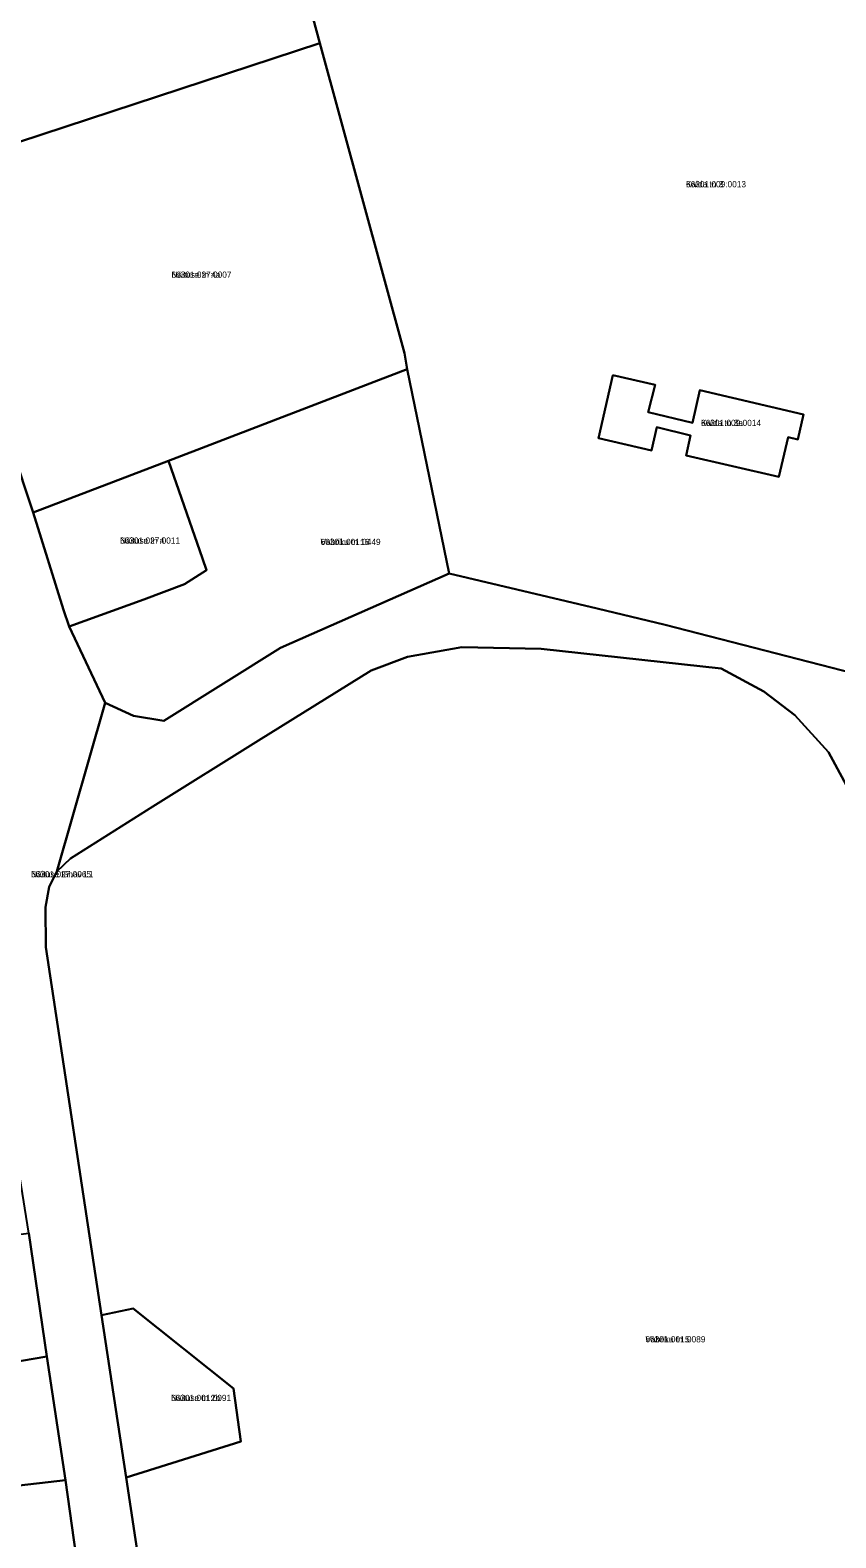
# Model space of a CAD drawing. Extents: x 632278 to 636344, y 6578401 to 6583362.
# Drawn here: x 633522.9 to 633717.6, y 6581626.2 to 6581990.5 of the extents above; entities that cross this region are included whole.
import ezdxf

# ---------------------------------------------------------------- set-up
doc = ezdxf.new("R2010")
doc.units = 0
for name, color, linetype in [('L_AADRESS', 7, 'Continuous'), ('PIIR', 7, 'Continuous'), ('TUNNUS', 7, 'Continuous')]:
    doc.layers.add(name, color=color, linetype=linetype)

msp = doc.modelspace()

# ---------------------------------------------------------------- linework, layer by layer
at = {"layer": 'PIIR'}
for points in [[(633580.94, 6582031.55), (633734.4, 6582070.6), (633768.37, 6581915.77), (633747.48, 6581916.12), (633724.51, 6581834.37), (633676.34, 6581846.74), (633659.91, 6581850.73), (633624.16, 6581859.21), (633613.99, 6581908.56), (633613.38, 6581912.42), (633592.88, 6581987.35)], [(633580.94, 6582031.55), (633592.88, 6581987.35), (633503.33, 6581957.89), (633502.57, 6581960.28), (633498.8, 6581958.88), (633484.12, 6582006.27)], [(633592.88, 6581987.35), (633613.38, 6581912.42), (633613.99, 6581908.56), (633556.31, 6581886.43), (633523.61, 6581873.92), (633518.47, 6581889.48), (633513.31, 6581906.06), (633498.83, 6581952.55), (633504.43, 6581954.3), (633503.33, 6581957.89)], [(633532.27, 6581846.35), (633550.34, 6581852.9), (633560.17, 6581856.58), (633565.51, 6581859.97), (633564.51, 6581862.83), (633556.31, 6581886.43), (633613.99, 6581908.56), (633624.16, 6581859.21), (633583.41, 6581841.2), (633555.18, 6581823.56), (633547.82, 6581824.76), (633541, 6581827.9)], [(633663.7, 6581907.11), (633660.2, 6581891.85), (633673, 6581888.86), (633674.31, 6581894.5), (633682.49, 6581892.55), (633681.43, 6581887.7), (633703.77, 6581882.53), (633706.04, 6581892.14), (633708.39, 6581891.58), (633709.76, 6581897.6), (633684.73, 6581903.48), (633682.92, 6581895.61), (633672.19, 6581898.2), (633673.88, 6581904.76)], [(633663.7, 6581907.11), (633673.88, 6581904.76), (633672.19, 6581898.2), (633682.92, 6581895.61), (633684.73, 6581903.48), (633709.76, 6581897.6), (633708.39, 6581891.58), (633706.04, 6581892.14), (633703.77, 6581882.53), (633681.43, 6581887.7), (633682.49, 6581892.55), (633674.31, 6581894.5), (633673, 6581888.86), (633660.2, 6581891.85)], [(633556.31, 6581886.43), (633564.51, 6581862.83), (633565.51, 6581859.97), (633560.17, 6581856.58), (633550.34, 6581852.9), (633532.27, 6581846.35), (633530.92, 6581850.44), (633523.61, 6581873.92)], [(633441.05, 6581677.6), (633439.42, 6581689.21), (633522.55, 6581699.81), (633526.94, 6581670.03), (633512.23, 6581667.49), (633511.9, 6581669.49), (633496.87, 6581666.04), (633443.6, 6581659.61)], [(633546.05, 6581640.76), (633540.12, 6581679.97), (633547.76, 6581681.61), (633572, 6581662.29), (633573.76, 6581649.45)], [(633445.34, 6581642.81), (633443.6, 6581659.61), (633496.87, 6581666.04), (633511.9, 6581669.49), (633512.23, 6581667.49), (633526.94, 6581670.03), (633531.38, 6581640.09), (633446.66, 6581630.36)], [(633450.03, 6581608.95), (633447.34, 6581625.47), (633446.66, 6581630.36), (633531.38, 6581640.09), (633535.56, 6581610.73), (633451.66, 6581597.92)]]:
    msp.add_lwpolyline(points, close=True, dxfattribs=at)
for points in [[(633535.56, 6581610.73), (633531.38, 6581640.09), (633526.94, 6581670.03), (633522.55, 6581699.81), (633517.88, 6581729.04), (633513.64, 6581758.84), (633509.79, 6581784.45), (633508.31, 6581800.02), (633504.64, 6581836.77), (633504.37, 6581841.88), (633502.31, 6581851.17), (633501.36, 6581855.45), (633492.85, 6581893.71), (633482.39, 6581890.96), (633462.71, 6581965.22), (633473.75, 6581968.03), (633470.22, 6581978.42), (633462.31, 6582011.45)], [(633484.12, 6582006.27), (633498.8, 6581958.88), (633496.97, 6581958.43), (633498.83, 6581952.55), (633513.31, 6581906.06), (633518.47, 6581889.48), (633523.61, 6581873.92), (633530.92, 6581850.44), (633532.27, 6581846.35), (633541, 6581827.9), (633529.3, 6581787.15), (633527.44, 6581783.44), (633526.6, 6581778.55), (633526.67, 6581768.89), (633540.12, 6581679.97), (633546.05, 6581640.76), (633561.16, 6581540.69)], [(633721.74, 6581804.98), (633715.84, 6581815.99), (633707.68, 6581824.93), (633700.19, 6581830.63), (633689.9, 6581836.23), (633646.37, 6581840.96), (633627.16, 6581841.42), (633614.03, 6581839.03), (633605.28, 6581835.77), (633578.09, 6581818.79), (633552.56, 6581802.88), (633532.6, 6581790.32), (633529.3, 6581787.15), (633541, 6581827.9), (633547.82, 6581824.76), (633555.18, 6581823.56), (633583.41, 6581841.2), (633624.16, 6581859.21), (633659.91, 6581850.73), (633676.34, 6581846.74), (633724.51, 6581834.37)], [(633561.16, 6581540.69), (633546.05, 6581640.76), (633573.76, 6581649.45), (633572, 6581662.29), (633547.76, 6581681.61), (633540.12, 6581679.97), (633526.67, 6581768.89), (633526.6, 6581778.55), (633527.44, 6581783.44), (633529.3, 6581787.15), (633532.6, 6581790.32), (633552.56, 6581802.88), (633578.09, 6581818.79), (633605.28, 6581835.77), (633614.03, 6581839.03), (633627.16, 6581841.42), (633646.37, 6581840.96), (633689.9, 6581836.23), (633700.19, 6581830.63), (633707.68, 6581824.93), (633715.84, 6581815.99), (633721.74, 6581804.98)]]:
    msp.add_lwpolyline(points, dxfattribs=at)

# ---------------------------------------------------------------- texts
at = {"layer": 'L_AADRESS'}
for s, p in [('Kalda tn 3', (633681.37, 6581952.49)), ('Näituse tn 4a', (633557.03, 6581930.64)), ('Kalda tn 3a', (633685, 6581894.82)), ('Näituse tn 4', (633544.61, 6581866.39)), ('Vabriku tn 16', (633593.07, 6581866.06)), ('Näituse tänav L1', (633523.1, 6581785.77)), ('Vabriku tn 5', (633671.56, 6581673.4)), ('Näituse tn 2b', (633556.94, 6581659.23))]:
    msp.add_text(s, height=1.5, dxfattribs=at).set_placement(p)
at = {"layer": 'TUNNUS'}
for s, p in [('66301:009:0013', (633681.37, 6581952.49)), ('66301:027:0007', (633557.03, 6581930.64)), ('66301:009:0014', (633685, 6581894.82)), ('66301:027:0011', (633544.61, 6581866.39)), ('66301:001:0449', (633593.07, 6581866.06)), ('66301:027:0065', (633523.1, 6581785.77)), ('66301:001:0089', (633671.56, 6581673.4)), ('66301:001:0091', (633556.94, 6581659.23))]:
    msp.add_text(s, height=1.5, dxfattribs=at).set_placement(p)

doc.saveas('drawing.dxf')
